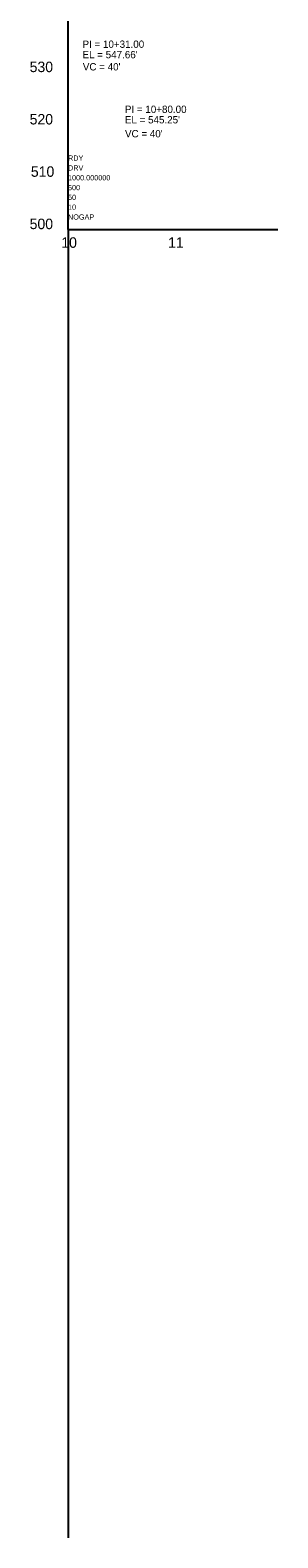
# Model space of a CAD drawing. Extents: x 1736530 to 1739201, y 695175 to 699135.
# Drawn here: x 1738963 to 1739199, y 695175 to 696615 of the extents above; entities that cross this region are included whole.
import ezdxf

# ---------------------------------------------------------------- set-up
doc = ezdxf.new("R2010")
doc.units = 0
for name, color, linetype in [('Exist Profile Cell', 7, 'Continuous'), ('Exist Vertical Profile Horizontal Axis Label Major', 7, 'Continuous'), ('Exist Vertical Profile Vertical Axis Label', 7, 'Continuous'), ('Prop Vertical Profile Curve Label', 7, 'Continuous'), ('Prop VPI Label', 7, 'Continuous')]:
    doc.layers.add(name, color=color, linetype=linetype)

msp = doc.modelspace()

# ---------------------------------------------------------------- linework, layer by layer
at = {"layer": 'Exist Profile Cell'}
for q in [(1738999.2, 697674.5), (1739199.2, 696424.5), (1738999.2, 695174.5)]:
    msp.add_line((1738999.2, 696424.5), q, dxfattribs=at)

# ---------------------------------------------------------------- texts
for s, p in [('RDY', (1738999.2, 696490.2)), ('DRV', (1738999.2, 696480.8)), ('500', (1738999.2, 696462)), ('1000.000000', (1738999.2, 696471.4)), ('50', (1738999.2, 696452.7)), ('10', (1738999.2, 696443.3)), ('NOGAP', (1738999.2, 696433.9))]:
    msp.add_text(s, height=5, dxfattribs=at).set_placement(p)
at = {"layer": 'Exist Vertical Profile Horizontal Axis Label Major'}
for s, p in [('10', (1738992.8, 696407)), ('11', (1739094.6, 696407))]:
    msp.add_text(s, height=10, dxfattribs=at).set_placement(p)
at = {"layer": 'Exist Vertical Profile Vertical Axis Label'}
for s, p in [('530', (1738962.6, 696574.8)), ('520', (1738962.6, 696524.8)), ('510', (1738963.8, 696474.8)), ('500', (1738962.6, 696424.8))]:
    msp.add_text(s, height=10, dxfattribs=at).set_placement(p)
at = {"layer": 'Prop Vertical Profile Curve Label'}
for p in [(1739013.3, 696576.4), (1739053.5, 696512.5)]:
    msp.add_text("VC = 40'", height=7, dxfattribs=at).set_placement(p)
at = {"layer": 'Prop VPI Label'}
for s, p in [('PI = 10+31.00', (1739013, 696598)), ("EL = 547.66'", (1739013, 696588)), ('PI = 10+80.00', (1739053.4, 696535.8)), ("EL = 545.25'", (1739053.4, 696525.8))]:
    msp.add_text(s, height=7, dxfattribs=at).set_placement(p)

doc.saveas('drawing.dxf')
